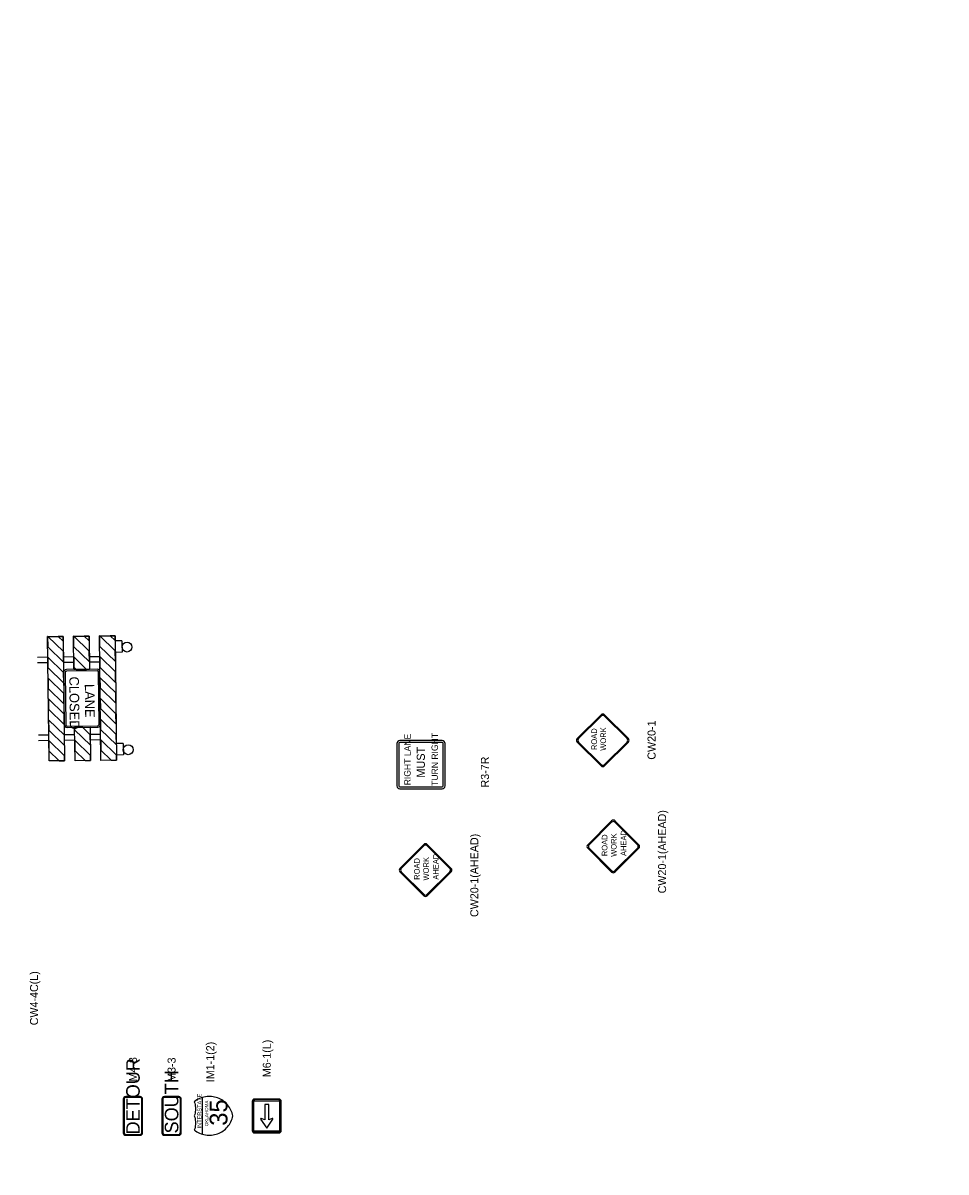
# Model space of a CAD drawing. Extents: x 2135767 to 2151731, y 141839 to 175894.
# Drawn here: x 2138549 to 2139087, y 170041 to 170711 of the extents above; entities that cross this region are included whole.
import ezdxf

# ---------------------------------------------------------------- set-up
doc = ezdxf.new("R2010")
doc.units = 0
for name, color, linetype in [('5', 7, 'Continuous'), ('6', 7, 'Continuous'), ('Default', 7, 'Continuous'), ('PR_Phasing_Detour_1', 7, 'Continuous'), ('PR_Txt', 7, 'Continuous')]:
    doc.layers.add(name, color=color, linetype=linetype)

msp = doc.modelspace()

# ---------------------------------------------------------------- linework, layer by layer
at = {"layer": '5'}
for p, q in [((2138607.81, 170083.67), (2138607.81, 170063.98)), ((2138617.19, 170084.61), (2138608.75, 170084.61)), ((2138618.13, 170063.98), (2138618.13, 170083.67)), ((2138630.31, 170083.67), (2138630.31, 170063.98)), ((2138639.69, 170084.61), (2138631.25, 170084.61)), ((2138640.63, 170063.98), (2138640.63, 170083.67)), ((2138653.41, 170063.16), (2138653.41, 170084.58)), ((2138698.11, 170083.67), (2138683.73, 170083.67)), ((2138682.48, 170082.42), (2138682.48, 170065.23)), ((2138699.35, 170065.23), (2138699.35, 170082.42)), ((2138683.73, 170063.98), (2138698.11, 170063.98)), ((2138608.75, 170063.05), (2138617.19, 170063.05)), ((2138631.25, 170063.05), (2138639.69, 170063.05))]:
    msp.add_line(p, q, dxfattribs=at)
msp.add_lwpolyline([(2138648.72, 170065.6), (2138649.44, 170065.07), (2138650.19, 170064.58), (2138650.98, 170064.14), (2138651.79, 170063.76), (2138652.62, 170063.42), (2138653.47, 170063.14), (2138654.34, 170062.92), (2138655.22, 170062.75), (2138656.11, 170062.64), (2138657, 170062.58), (2138657.9, 170062.58), (2138658.8, 170062.64), (2138659.68, 170062.75), (2138660.56, 170062.93), (2138661.43, 170063.15), (2138662.28, 170063.44), (2138663.11, 170063.77), (2138663.92, 170064.16), (2138664.7, 170064.6), (2138665.46, 170065.09), (2138666.18, 170065.62), (2138666.86, 170066.2), (2138667.51, 170066.82), (2138668.11, 170067.48), (2138668.67, 170068.18), (2138669.19, 170068.92), (2138669.66, 170069.68), (2138670.07, 170070.48), (2138670.44, 170071.29), (2138670.76, 170072.13), (2138671.02, 170072.99), (2138671.22, 170073.86), (2138671.02, 170074.74), (2138670.76, 170075.6), (2138670.44, 170076.43), (2138670.07, 170077.25), (2138669.66, 170078.05), (2138669.19, 170078.81), (2138668.67, 170079.54), (2138668.11, 170080.24), (2138667.51, 170080.91), (2138666.86, 170081.53), (2138666.18, 170082.11), (2138665.46, 170082.64), (2138664.7, 170083.13), (2138663.92, 170083.57), (2138663.11, 170083.96), (2138662.28, 170084.29), (2138661.43, 170084.57), (2138660.56, 170084.8), (2138659.68, 170084.97), (2138658.8, 170085.09), (2138657.9, 170085.15), (2138657, 170085.15), (2138656.11, 170085.09), (2138655.22, 170084.98), (2138654.34, 170084.81), (2138653.47, 170084.58), (2138652.62, 170084.31), (2138651.79, 170083.97), (2138650.98, 170083.59), (2138650.19, 170083.15), (2138649.44, 170082.66), (2138648.72, 170082.13), (2138648.94, 170081.32), (2138649.12, 170080.5), (2138649.24, 170079.67), (2138649.32, 170078.84), (2138649.34, 170078), (2138649.32, 170077.16), (2138649.24, 170076.32), (2138649.12, 170075.49), (2138648.94, 170074.67), (2138648.72, 170073.86), (2138648.94, 170073.06), (2138649.12, 170072.23), (2138649.24, 170071.41), (2138649.32, 170070.57), (2138649.34, 170069.73), (2138649.32, 170068.89), (2138649.24, 170068.06), (2138649.12, 170067.23), (2138648.94, 170066.41), (2138648.72, 170065.6)], dxfattribs=at)
for centre, radius, start, end in [((2138608.75, 170083.67), 0.937, 90, 180), ((2138617.19, 170083.67), 0.937, 360, 90), ((2138631.25, 170083.67), 0.937, 90, 180), ((2138639.69, 170083.67), 0.937, 360, 90), ((2138683.73, 170082.42), 1.25, 90, 180), ((2138698.11, 170082.42), 1.25, 360, 90), ((2138608.75, 170063.98), 0.937, 180, 270), ((2138617.19, 170063.98), 0.937, 270, 360), ((2138631.25, 170063.98), 0.937, 180, 270), ((2138639.69, 170063.98), 0.937, 270, 360), ((2138683.73, 170065.23), 1.25, 180, 270), ((2138698.11, 170065.23), 1.25, 270, 360)]:
    msp.add_arc(centre, radius, start, end, dxfattribs=at)
at = {"layer": '6'}
for p, q in [((2138607.35, 170083.67), (2138607.35, 170063.98)), ((2138617.19, 170085.08), (2138608.75, 170085.08)), ((2138618.6, 170063.98), (2138618.6, 170083.67)), ((2138629.85, 170083.67), (2138629.85, 170063.98)), ((2138639.69, 170085.08), (2138631.25, 170085.08)), ((2138641.1, 170063.98), (2138641.1, 170083.67)), ((2138608.75, 170062.58), (2138617.19, 170062.58)), ((2138631.25, 170062.58), (2138639.69, 170062.58))]:
    msp.add_line(p, q, dxfattribs=at)
for centre, start, end in [((2138608.75, 170083.67), 90, 180), ((2138617.19, 170083.67), 360, 90), ((2138631.25, 170083.67), 90, 180), ((2138639.69, 170083.67), 360, 90), ((2138608.75, 170063.98), 180, 270), ((2138617.19, 170063.98), 270, 360), ((2138631.25, 170063.98), 180, 270), ((2138639.69, 170063.98), 270, 360)]:
    msp.add_arc(centre, 1.41, start, end, dxfattribs=at)
at = {"layer": 'Default'}
for p, q in [((2138572.6, 170332.37), (2138572.97, 170301.8)), ((2138573.45, 170332.38), (2138573.82, 170301.81)), ((2138592.09, 170334.18), (2138574.17, 170333.97)), ((2138592.1, 170333.34), (2138574.18, 170333.12)), ((2138593.21, 170302.04), (2138592.84, 170332.61)), ((2138594.05, 170302.05), (2138593.69, 170332.62)), ((2138885.64, 170307.68), (2138871.72, 170293.76)), ((2138872.52, 170293.76), (2138885.64, 170306.88)), ((2138901.55, 170293.76), (2138887.63, 170307.68)), ((2138887.63, 170306.88), (2138900.76, 170293.76)), ((2138574.56, 170301.08), (2138592.48, 170301.29)), ((2138574.57, 170300.23), (2138592.49, 170300.45)), ((2138793.07, 170292.6), (2138768.46, 170292.6)), ((2138793.07, 170291.47), (2138768.46, 170291.47)), ((2138871.72, 170291.77), (2138885.64, 170277.85)), ((2138885.64, 170278.64), (2138872.52, 170291.77)), ((2138900.76, 170291.77), (2138887.63, 170278.64)), ((2138887.63, 170277.85), (2138901.55, 170291.77)), ((2138766.7, 170290.84), (2138766.7, 170266.23)), ((2138767.83, 170290.84), (2138767.83, 170266.23)), ((2138793.7, 170266.23), (2138793.7, 170290.84)), ((2138794.83, 170266.23), (2138794.83, 170290.84)), ((2138768.46, 170265.6), (2138793.07, 170265.6)), ((2138768.46, 170264.47), (2138793.07, 170264.47)), ((2138891.76, 170245.83), (2138877.84, 170231.91)), ((2138891.76, 170245.03), (2138878.64, 170231.91)), ((2138907.67, 170231.91), (2138893.75, 170245.83)), ((2138906.88, 170231.91), (2138893.75, 170245.03)), ((2138782.42, 170232.05), (2138768.5, 170218.12)), ((2138782.42, 170231.25), (2138769.29, 170218.12)), ((2138798.33, 170218.12), (2138784.41, 170232.05)), ((2138797.53, 170218.12), (2138784.41, 170231.25)), ((2138877.84, 170229.92), (2138891.76, 170216)), ((2138878.64, 170229.92), (2138891.76, 170216.79)), ((2138893.75, 170216.79), (2138906.88, 170229.92)), ((2138893.75, 170216), (2138907.67, 170229.92)), ((2138768.5, 170216.14), (2138782.42, 170202.21)), ((2138769.29, 170216.14), (2138782.42, 170203.01)), ((2138784.41, 170203.01), (2138797.53, 170216.14)), ((2138784.41, 170202.21), (2138798.33, 170216.14)), ((2138682.83, 170082.42), (2138682.83, 170065.23)), ((2138682.83, 170082.42), (2138682.83, 170065.23)), ((2138683.42, 170065.23), (2138683.42, 170082.42)), ((2138683.42, 170065.23), (2138683.42, 170082.42)), ((2138698.11, 170083.32), (2138683.73, 170083.32)), ((2138698.11, 170083.32), (2138683.73, 170083.32)), ((2138683.73, 170082.73), (2138698.11, 170082.73)), ((2138683.73, 170082.73), (2138698.11, 170082.73)), ((2138692.11, 170080.51), (2138689.72, 170080.51)), ((2138689.72, 170080.51), (2138689.72, 170071.59)), ((2138692.11, 170071.59), (2138692.11, 170080.51)), ((2138698.42, 170082.42), (2138698.42, 170065.23)), ((2138698.42, 170082.42), (2138698.42, 170065.23)), ((2138699, 170065.23), (2138699, 170082.42)), ((2138699, 170065.23), (2138699, 170082.42)), ((2138687.32, 170071.99), (2138690.92, 170066.8)), ((2138689.72, 170071.59), (2138687.72, 170072.39)), ((2138690.92, 170066.8), (2138694.51, 170071.99)), ((2138694.11, 170072.39), (2138692.11, 170071.59)), ((2138698.11, 170064.92), (2138683.73, 170064.92)), ((2138698.11, 170064.92), (2138683.73, 170064.92)), ((2138683.73, 170064.33), (2138698.11, 170064.33)), ((2138683.73, 170064.33), (2138698.11, 170064.33))]:
    msp.add_line(p, q, dxfattribs=at)
for points in [[(2138563.4, 170341.15), (2138557.35, 170341.08)], [(2138557.39, 170338.05), (2138563.43, 170338.13)], [(2138578.51, 170341.33), (2138572.46, 170341.26)], [(2138572.5, 170338.24), (2138578.54, 170338.31)], [(2138593.62, 170341.51), (2138587.57, 170341.44)], [(2138587.61, 170338.42), (2138593.65, 170338.49)], [(2138563.94, 170295.82), (2138557.9, 170295.74)], [(2138557.93, 170292.72), (2138563.98, 170292.8)], [(2138579.05, 170296), (2138573.01, 170295.93)], [(2138573.04, 170292.9), (2138579.09, 170292.98)], [(2138594.16, 170296.18), (2138588.12, 170296.11)], [(2138588.15, 170293.09), (2138594.2, 170293.16)], [(2138694.11, 170072.39), (2138692.11, 170071.59), (2138692.11, 170080.51), (2138689.72, 170080.51), (2138689.72, 170071.59), (2138687.72, 170072.39)], [(2138687.32, 170071.99), (2138690.92, 170066.8)], [(2138690.92, 170066.8), (2138694.51, 170071.99)]]:
    msp.add_lwpolyline(points, dxfattribs=at)
for centre, radius, start, end in [((2138574.19, 170332.39), 1.58, 90.68953, 180.68953), ((2138574.19, 170332.39), 0.738, 90.68953, 180.68953), ((2138592.11, 170332.6), 1.58, 0.68953, 90.68953), ((2138592.11, 170332.6), 0.738, 0.68953, 90.68953), ((2138886.64, 170306.68), 1.41, 45, 135), ((2138886.64, 170305.89), 1.41, 45, 135), ((2138574.55, 170301.82), 1.58, 180.68953, 270.68953), ((2138574.55, 170301.82), 0.738, 180.68953, 270.68953), ((2138592.47, 170302.03), 0.738, 270.68953, 0.68953), ((2138592.47, 170302.03), 1.58, 270.68953, 0.68953), ((2138768.46, 170290.84), 1.76, 90, 180), ((2138768.46, 170290.84), 0.633, 90, 180), ((2138793.07, 170290.84), 1.76, 360, 90), ((2138793.07, 170290.84), 0.633, 360, 90), ((2138872.72, 170292.76), 1.41, 135, 225), ((2138873.51, 170292.76), 1.41, 135, 225), ((2138899.76, 170292.76), 1.41, 315, 45), ((2138900.56, 170292.76), 1.41, 315, 45), ((2138886.64, 170279.64), 1.41, 225, 315), ((2138886.64, 170278.84), 1.41, 225, 315), ((2138768.46, 170266.23), 1.76, 180, 270), ((2138768.46, 170266.23), 0.633, 180, 270), ((2138793.07, 170266.23), 0.633, 270, 360), ((2138793.07, 170266.23), 1.76, 270, 360), ((2138892.76, 170244.83), 1.41, 45, 135), ((2138892.76, 170244.04), 1.41, 45, 135), ((2138783.41, 170231.05), 1.41, 45, 135), ((2138783.41, 170230.26), 1.41, 45, 135), ((2138878.84, 170230.91), 1.41, 135, 225), ((2138879.63, 170230.91), 1.41, 135, 225), ((2138905.88, 170230.91), 1.41, 315, 45), ((2138906.68, 170230.91), 1.41, 315, 45), ((2138769.49, 170217.13), 1.41, 135, 225), ((2138770.29, 170217.13), 1.41, 135, 225), ((2138796.54, 170217.13), 1.41, 315, 45), ((2138797.33, 170217.13), 1.41, 315, 45), ((2138892.76, 170217.79), 1.41, 225, 315), ((2138892.76, 170216.99), 1.41, 225, 315), ((2138783.41, 170204), 1.41, 225, 315), ((2138783.41, 170203.21), 1.41, 225, 315), ((2138683.73, 170082.42), 0.895, 90, 180), ((2138683.73, 170082.42), 0.895, 90, 180), ((2138683.73, 170082.42), 0.309, 90, 180), ((2138683.73, 170082.42), 0.309, 90, 180), ((2138698.11, 170082.42), 0.895, 360, 90), ((2138698.11, 170082.42), 0.895, 360, 90), ((2138698.11, 170082.42), 0.309, 360, 90), ((2138698.11, 170082.42), 0.309, 360, 90), ((2138687.72, 170071.99), 0.4, 90, 180), ((2138687.72, 170071.99), 0.4, 90, 180), ((2138694.11, 170071.99), 0.4, 360, 90), ((2138694.11, 170071.99), 0.4, 360, 90), ((2138683.73, 170065.23), 0.895, 180, 270), ((2138683.73, 170065.23), 0.895, 180, 270), ((2138683.73, 170065.23), 0.309, 180, 270), ((2138683.73, 170065.23), 0.309, 180, 270), ((2138698.11, 170065.23), 0.895, 270, 360), ((2138698.11, 170065.23), 0.309, 270, 360), ((2138698.11, 170065.23), 0.895, 270, 360), ((2138698.11, 170065.23), 0.309, 270, 360)]:
    msp.add_arc(centre, radius, start, end, dxfattribs=at)
at = {"layer": 'PR_Phasing_Detour_1'}
msp.add_circle((2140069.54, 171591.41), 4302.23, dxfattribs=at)
at = {"layer": 'PR_Txt'}
for p, q in [((2138606.59, 170350.76), (2138602.57, 170350.71)), ((2138606.59, 170350.76), (2138606.67, 170344.06)), ((2138606.67, 170344.06), (2138602.65, 170344.01)), ((2138607.31, 170290.93), (2138603.29, 170290.88)), ((2138607.31, 170290.93), (2138607.39, 170284.23)), ((2138607.39, 170284.23), (2138603.37, 170284.18))]:
    msp.add_line(p, q, dxfattribs=at)
for points in [[(2138572.32, 170353.35), (2138573.19, 170280.82), (2138564.12, 170280.71), (2138563.25, 170353.24)], [(2138563.43, 170353.24), (2138563.25, 170353.24), (2138563.32, 170347.32), (2138572.5, 170338.37), (2138572.42, 170344.46)], [(2138572.35, 170350.48), (2138572.32, 170353.35), (2138569.45, 170353.31)], [(2138587.43, 170353.53), (2138587.66, 170334.13), (2138578.59, 170334.02), (2138578.36, 170353.42)], [(2138578.54, 170353.42), (2138578.36, 170353.42), (2138578.43, 170347.5), (2138587.61, 170338.55), (2138587.53, 170344.65)], [(2138587.46, 170350.67), (2138587.43, 170353.53), (2138584.56, 170353.49)], [(2138602.54, 170353.71), (2138603.41, 170281.18), (2138594.34, 170281.07), (2138593.47, 170353.6)], [(2138593.66, 170353.6), (2138593.47, 170353.6), (2138593.54, 170347.69), (2138602.72, 170338.73), (2138602.64, 170344.83)], [(2138602.57, 170350.85), (2138602.54, 170353.71), (2138599.68, 170353.68)], [(2138563.39, 170341.23), (2138563.47, 170335.13), (2138572.64, 170326.17), (2138572.57, 170332.27)], [(2138578.51, 170341.41), (2138578.58, 170335.31), (2138579.88, 170334.04), (2138585.98, 170334.11)], [(2138593.62, 170341.59), (2138593.69, 170335.49), (2138602.86, 170326.53), (2138602.79, 170332.63)], [(2138563.54, 170328.99), (2138563.61, 170322.97), (2138572.79, 170314.02), (2138572.72, 170320.04)], [(2138593.76, 170329.36), (2138593.84, 170323.34), (2138603.01, 170314.38), (2138602.94, 170320.4)], [(2138563.69, 170316.88), (2138563.76, 170310.85), (2138572.94, 170301.9), (2138572.86, 170307.92)], [(2138593.91, 170317.24), (2138593.98, 170311.22), (2138603.16, 170302.26), (2138603.08, 170308.28)], [(2138563.83, 170304.76), (2138563.91, 170298.73), (2138573.08, 170289.78), (2138573.01, 170295.8)], [(2138594.05, 170305.12), (2138594.13, 170299.1), (2138603.3, 170290.14), (2138603.23, 170296.16)], [(2138588.07, 170300.4), (2138588.3, 170281), (2138579.23, 170280.89), (2138579, 170300.29)], [(2138583.65, 170300.34), (2138579, 170300.29), (2138579.02, 170298.92), (2138588.19, 170289.96), (2138588.12, 170295.98)], [(2138563.98, 170292.64), (2138564.05, 170286.62), (2138570.03, 170280.78), (2138573.19, 170280.82), (2138573.15, 170283.68)], [(2138579.09, 170292.82), (2138579.16, 170286.8), (2138585.14, 170280.96), (2138588.3, 170281), (2138588.27, 170283.86)], [(2138594.2, 170293), (2138594.27, 170286.98), (2138600.25, 170281.14), (2138603.41, 170281.18), (2138603.38, 170284.04)]]:
    msp.add_lwpolyline(points, close=True, dxfattribs=at)
for centre in [(2138609.51, 170347.12), (2138610.23, 170287.3)]:
    msp.add_circle(centre, 2.9, dxfattribs=at)

# ---------------------------------------------------------------- texts
at = {"layer": 'Default'}
for s, height, rotation, p in [('CLOSED', 5.622, 270.68953, (2138575.87, 170329.91)), ('LANE', 5.622, 270.68953, (2138584.92, 170325.59)), ('ROAD', 3.281, 90, (2138883.22, 170287.09)), ('WORK', 3.281, 90, (2138888.56, 170286.7)), ('CW20-1', 4.664, 90, (2138917.38, 170281.46)), ('RIGHT LANE', 3.742, 90, (2138774.7, 170266.55)), ('TURN RIGHT', 3.742, 90, (2138790.62, 170266.21)), ('MUST', 4.751, 90, (2138783.03, 170271.01)), ('R3-7R', 4.664, 90, (2138820.33, 170265.26)), ('CW20-1(AHEAD)', 4.6644, 90, (2138923.5, 170203.56)), ('CW20-1(AHEAD)', 4.6644, 90, (2138814.15, 170189.77)), ('ROAD', 3.281, 90, (2138889.34, 170225.25)), ('WORK', 3.281, 90, (2138894.68, 170224.86)), ('AHEAD', 3.281, 90, (2138900.37, 170225.34)), ('WORK', 3.281, 90, (2138785.34, 170211.07)), ('AHEAD', 3.281, 90, (2138791.02, 170211.55)), ('ROAD', 3.281, 90, (2138780, 170211.46)), ('CW4-4C(L)', 4.664, 90, (2138557.69, 170126.66)), ('M6-1(L)', 4.664, 90, (2138693.25, 170096.42)), ('IM1-1(2)', 4.664, 90, (2138660.3, 170093.5)), ('DETOUR', 7.875, 90, (2138616.91, 170063.05)), ('M4-8', 4.664, 90, (2138615.3, 170093.89)), ('M3-3', 4.664, 90, (2138637.8, 170093.69)), ('SOUTH', 7.875, 90, (2138639.41, 170063.64)), ('INTERSTATE', 2.352, 90, (2138652.89, 170066.59)), ('OKLAHOMA', 1.906, 90, (2138656.79, 170067.84)), ('35', 10.35, 90, (2138668, 170068.12))]:
    msp.add_text(s, height=height, rotation=rotation, dxfattribs=at).set_placement(p)

doc.saveas('drawing.dxf')
